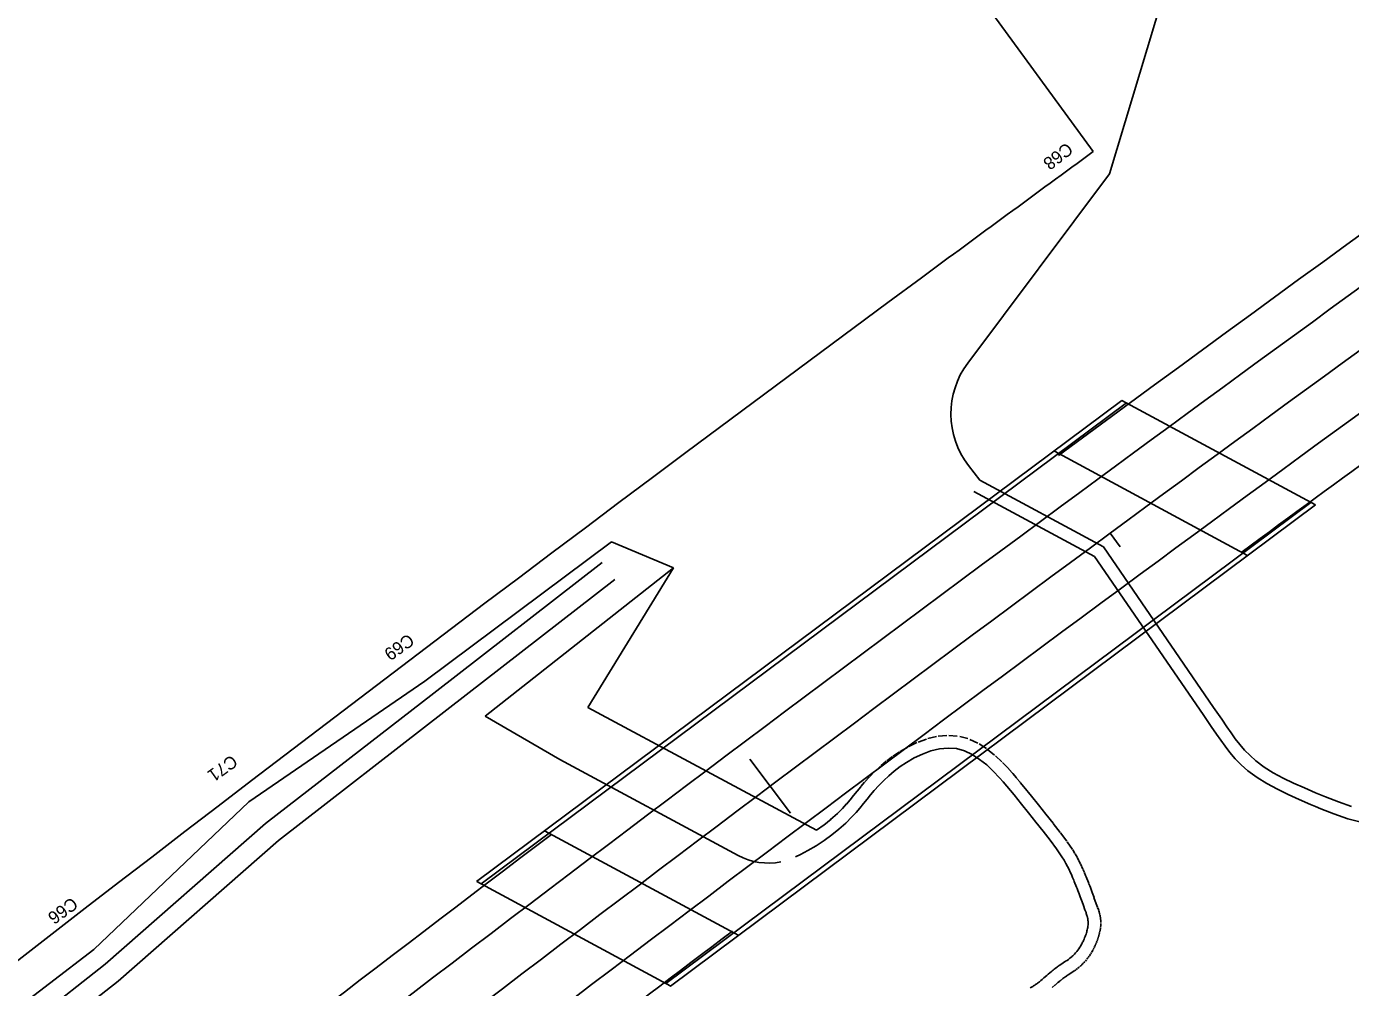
# Model space of a CAD drawing. Extents: x 1469024 to 1473560, y 1105695 to 1109739.
# Drawn here: x 1470861.2 to 1471173.7, y 1107588.4 to 1107815.4 of the extents above; entities that cross this region are included whole.
import ezdxf

# ---------------------------------------------------------------- set-up
doc = ezdxf.new("R2010")
doc.units = 0
for name, color, linetype in [('RD_HC_CL_Rel', 7, 'Continuous'), ('RD_HC_Data_Tic_Rel', 7, 'Continuous'), ('RD_PD_Bridge', 7, 'Continuous'), ('RD_PD_CstnLmt', 7, 'Continuous'), ('RD_PD_CstnLmt_TX', 7, 'Continuous'), ('RD_PD_DR_Ditch', 7, 'Continuous'), ('RD_PD_DR_ErosCtrl', 7, 'Continuous'), ('RD_PD_Final_TrvlWay', 7, 'Continuous'), ('RD_PD_GR', 7, 'Continuous'), ('RD_PD_RW', 7, 'Continuous')]:
    doc.layers.add(name, color=color, linetype=linetype)

msp = doc.modelspace()

# ---------------------------------------------------------------- linework, layer by layer
at = {"layer": 'RD_HC_CL_Rel'}
for start, end in [(123.079489, 126.41418), (126.41418, 130.102414)]:
    msp.add_arc((1477943.58, 1098441.09), 11500, start, end, dxfattribs=at)
at = {"layer": 'RD_HC_Data_Tic_Rel'}
for p, q in [((1471116.97, 1107695.68), (1471119.34, 1107692.46)), ((1471036.75, 1107635.97), (1471031.95, 1107642.36)), ((1471036.75, 1107635.97), (1471041.56, 1107629.57))]:
    msp.add_line(p, q, dxfattribs=at)
at = {"layer": 'RD_PD_Bridge'}
for p, q in [((1470967.44, 1107613.45), (1471119.73, 1107727.07)), ((1471119.73, 1107727.07), (1471165.47, 1107702.37)), ((1470968.54, 1107612.86), (1471120.82, 1107726.48)), ((1471103.83, 1107715.06), (1471149.46, 1107690.41)), ((1471012.11, 1107589.33), (1471164.39, 1107702.95)), ((1471013.2, 1107588.74), (1471165.48, 1107702.36)), ((1470983.45, 1107625.44), (1471029.3, 1107600.68)), ((1470967.52, 1107613.41), (1471013.27, 1107588.7))]:
    msp.add_line(p, q, dxfattribs=at)
at = {"layer": 'RD_PD_CstnLmt'}
for p, q in [((1471135.06, 1107841.18), (1471116.88, 1107780.53)), ((1471116.88, 1107780.53), (1471083.39, 1107735.89)), ((1471086.23, 1107708.2), (1471083.55, 1107711.67)), ((1471115.39, 1107692.51), (1471086.23, 1107708.2)), ((1470955.2, 1107660.78), (1470999.28, 1107693.67)), ((1470999.28, 1107693.67), (1471013.93, 1107687.49)), ((1471013.93, 1107687.49), (1470969.48, 1107652.47)), ((1470913.68, 1107632.27), (1470955.2, 1107660.78)), ((1471068.9, 1107641.54), (1471070.74, 1107642.61)), ((1471070.74, 1107642.61), (1471072.68, 1107643.53)), ((1471072.68, 1107643.53), (1471074.68, 1107644.26)), ((1471074.68, 1107644.26), (1471076.7, 1107644.75)), ((1471076.7, 1107644.75), (1471078.72, 1107644.95)), ((1471078.72, 1107644.95), (1471080.69, 1107644.81)), ((1471080.69, 1107644.81), (1471082.61, 1107644.28)), ((1471082.61, 1107644.28), (1471084.44, 1107643.42)), ((1471084.44, 1107643.42), (1471086.19, 1107642.29)), ((1471064.75, 1107638.43), (1471066.04, 1107639.52)), ((1471066.04, 1107639.52), (1471067.43, 1107640.56)), ((1471067.43, 1107640.56), (1471068.9, 1107641.54)), ((1471086.19, 1107642.29), (1471087.85, 1107640.96)), ((1471087.85, 1107640.96), (1471089.41, 1107639.49)), ((1471089.41, 1107639.49), (1471090.87, 1107637.95)), ((1471062.39, 1107636.14), (1471063.53, 1107637.3)), ((1471063.53, 1107637.3), (1471064.75, 1107638.43)), ((1471090.87, 1107637.95), (1471091.76, 1107636.96)), ((1471091.76, 1107636.96), (1471092.62, 1107635.96)), ((1471059.6, 1107632.89), (1471060.45, 1107633.93)), ((1471060.45, 1107633.93), (1471061.31, 1107634.95)), ((1471061.31, 1107634.95), (1471062.39, 1107636.14)), ((1471092.62, 1107635.96), (1471093.47, 1107634.94)), ((1471093.47, 1107634.94), (1471094.31, 1107633.9)), ((1471094.31, 1107633.9), (1471096.07, 1107631.72)), ((1470877.09, 1107597.35), (1470913.68, 1107632.27)), ((1471057.01, 1107629.74), (1471057.91, 1107630.79)), ((1471057.91, 1107630.79), (1471058.76, 1107631.84)), ((1471058.76, 1107631.84), (1471059.6, 1107632.89)), ((1471096.07, 1107631.72), (1471097.74, 1107629.65)), ((1471052.98, 1107625.81), (1471054.58, 1107627.24)), ((1471054.58, 1107627.24), (1471056.04, 1107628.69)), ((1471056.04, 1107628.69), (1471057.01, 1107629.74)), ((1471097.74, 1107629.65), (1471099.48, 1107627.49)), ((1471099.48, 1107627.49), (1471101.21, 1107625.31)), ((1471049.46, 1107623.11), (1471051.27, 1107624.43)), ((1471051.27, 1107624.43), (1471052.98, 1107625.81)), ((1471101.21, 1107625.31), (1471102.85, 1107623.18)), ((1471043.86, 1107619.79), (1471045.66, 1107620.74)), ((1471045.66, 1107620.74), (1471047.59, 1107621.87)), ((1471047.59, 1107621.87), (1471049.46, 1107623.11)), ((1471102.85, 1107623.18), (1471104.34, 1107621.16)), ((1471104.34, 1107621.16), (1471105.6, 1107619.3)), ((1471042.75, 1107619.25), (1471043.86, 1107619.79)), ((1471105.6, 1107619.3), (1471106.12, 1107618.47)), ((1471106.12, 1107618.47), (1471106.57, 1107617.69)), ((1471106.57, 1107617.69), (1471106.96, 1107616.96)), ((1471106.96, 1107616.96), (1471107.3, 1107616.29)), ((1471107.3, 1107616.29), (1471107.59, 1107615.67)), ((1471107.59, 1107615.67), (1471107.84, 1107615.11)), ((1471107.84, 1107615.11), (1471107.95, 1107614.85)), ((1471107.95, 1107614.85), (1471108.14, 1107614.38)), ((1471108.14, 1107614.38), (1471108.41, 1107613.73)), ((1471108.41, 1107613.73), (1471108.53, 1107613.44)), ((1471108.53, 1107613.44), (1471109.09, 1107612.08)), ((1471109.09, 1107612.08), (1471109.19, 1107611.81)), ((1471109.19, 1107611.81), (1471109.38, 1107611.35)), ((1471109.38, 1107611.35), (1471109.53, 1107610.95)), ((1471109.53, 1107610.95), (1471109.68, 1107610.54)), ((1471109.68, 1107610.54), (1471109.93, 1107609.84)), ((1471109.93, 1107609.84), (1471110.36, 1107608.63)), ((1471110.36, 1107608.63), (1471110.67, 1107607.78)), ((1471110.67, 1107607.78), (1471111.05, 1107606.75)), ((1471111.05, 1107606.75), (1471111.22, 1107606.3)), ((1471111.22, 1107606.3), (1471111.3, 1107606.08)), ((1471111.3, 1107606.08), (1471111.37, 1107605.86)), ((1471111.37, 1107605.86), (1471111.45, 1107605.64)), ((1471111.45, 1107605.64), (1471111.52, 1107605.41)), ((1471111.52, 1107605.41), (1471111.56, 1107605.28)), ((1471111.56, 1107605.28), (1471111.6, 1107605.14)), ((1471111.6, 1107605.14), (1471111.63, 1107605)), ((1471111.63, 1107605), (1471111.66, 1107604.85)), ((1471111.59, 1107602), (1471111.53, 1107601.75)), ((1471111.65, 1107602.31), (1471111.59, 1107602)), ((1471111.7, 1107602.61), (1471111.65, 1107602.31)), ((1471111.66, 1107604.85), (1471111.69, 1107604.71)), ((1471111.69, 1107604.71), (1471111.72, 1107604.57)), ((1471111.74, 1107602.92), (1471111.7, 1107602.61)), ((1471111.72, 1107604.57), (1471111.74, 1107604.44)), ((1471111.74, 1107604.44), (1471111.75, 1107604.32)), ((1471111.77, 1107603.22), (1471111.74, 1107602.92)), ((1471111.75, 1107604.32), (1471111.76, 1107604.19)), ((1471111.76, 1107604.19), (1471111.77, 1107604.06)), ((1471111.77, 1107604.06), (1471111.78, 1107603.93)), ((1471111.78, 1107603.51), (1471111.77, 1107603.22)), ((1471111.78, 1107603.93), (1471111.79, 1107603.8)), ((1471111.79, 1107603.8), (1471111.78, 1107603.51)), ((1471110.4, 1107598.89), (1471110.29, 1107598.69)), ((1471110.5, 1107599.1), (1471110.4, 1107598.89)), ((1471110.61, 1107599.3), (1471110.5, 1107599.1)), ((1471110.7, 1107599.51), (1471110.61, 1107599.3)), ((1471110.84, 1107599.82), (1471110.7, 1107599.51)), ((1471110.97, 1107600.12), (1471110.84, 1107599.82)), ((1471111.1, 1107600.42), (1471110.97, 1107600.12)), ((1471111.21, 1107600.72), (1471111.1, 1107600.42)), ((1471111.31, 1107601.03), (1471111.21, 1107600.72)), ((1471111.41, 1107601.33), (1471111.31, 1107601.03)), ((1471111.46, 1107601.49), (1471111.41, 1107601.33)), ((1471111.53, 1107601.75), (1471111.46, 1107601.49)), ((1470837.12, 1107566.82), (1470877.09, 1107597.35)), ((1471107.93, 1107595.66), (1471107.8, 1107595.55)), ((1471108.06, 1107595.77), (1471107.93, 1107595.66)), ((1471108.19, 1107595.89), (1471108.06, 1107595.77)), ((1471108.31, 1107596.01), (1471108.19, 1107595.89)), ((1471108.43, 1107596.13), (1471108.31, 1107596.01)), ((1471108.55, 1107596.25), (1471108.43, 1107596.13)), ((1471108.83, 1107596.56), (1471108.55, 1107596.25)), ((1471109.1, 1107596.89), (1471108.83, 1107596.56)), ((1471109.36, 1107597.23), (1471109.1, 1107596.89)), ((1471109.61, 1107597.57), (1471109.36, 1107597.23)), ((1471109.84, 1107597.92), (1471109.61, 1107597.57)), ((1471110.06, 1107598.28), (1471109.84, 1107597.92)), ((1471110.17, 1107598.48), (1471110.06, 1107598.28)), ((1471110.29, 1107598.69), (1471110.17, 1107598.48)), ((1471103.56, 1107592.53), (1471103.32, 1107592.34)), ((1471103.81, 1107592.72), (1471103.56, 1107592.53)), ((1471104.05, 1107592.91), (1471103.81, 1107592.72)), ((1471104.3, 1107593.09), (1471104.05, 1107592.91)), ((1471104.55, 1107593.27), (1471104.3, 1107593.09)), ((1471104.76, 1107593.42), (1471104.55, 1107593.27)), ((1471104.97, 1107593.57), (1471104.76, 1107593.42)), ((1471105.39, 1107593.85), (1471104.97, 1107593.57)), ((1471106.49, 1107594.59), (1471105.39, 1107593.85)), ((1471106.83, 1107594.82), (1471106.49, 1107594.59)), ((1471107.16, 1107595.05), (1471106.83, 1107594.82)), ((1471107.48, 1107595.3), (1471107.16, 1107595.05)), ((1471107.8, 1107595.55), (1471107.48, 1107595.3)), ((1471099.85, 1107589.41), (1471099.69, 1107589.3)), ((1471100, 1107589.52), (1471099.85, 1107589.41)), ((1471100.16, 1107589.64), (1471100, 1107589.52)), ((1471100.31, 1107589.76), (1471100.16, 1107589.64)), ((1471100.43, 1107589.86), (1471100.31, 1107589.76)), ((1471100.67, 1107590.06), (1471100.43, 1107589.86)), ((1471100.91, 1107590.26), (1471100.67, 1107590.06)), ((1471101.36, 1107590.65), (1471100.91, 1107590.26)), ((1471102.03, 1107591.24), (1471101.36, 1107590.65)), ((1471102.37, 1107591.55), (1471102.03, 1107591.24)), ((1471102.72, 1107591.85), (1471102.37, 1107591.55)), ((1471103.07, 1107592.14), (1471102.72, 1107591.85)), ((1471103.32, 1107592.34), (1471103.07, 1107592.14)), ((1471098.39, 1107588.48), (1471098.12, 1107588.33)), ((1471098.56, 1107588.58), (1471098.39, 1107588.48)), ((1471098.73, 1107588.67), (1471098.56, 1107588.58)), ((1471098.89, 1107588.77), (1471098.73, 1107588.67)), ((1471099.06, 1107588.87), (1471098.89, 1107588.77)), ((1471099.22, 1107588.98), (1471099.06, 1107588.87)), ((1471099.38, 1107589.08), (1471099.22, 1107588.98)), ((1471099.54, 1107589.19), (1471099.38, 1107589.08)), ((1471099.69, 1107589.3), (1471099.54, 1107589.19))]:
    msp.add_line(p, q, dxfattribs=at)
for points in [[(1471115.39, 1107692.51), (1471141.39, 1107654.57), (1471143.33, 1107651.74), (1471144.57, 1107649.94), (1471145.53, 1107648.56), (1471146.54, 1107647.17), (1471147.6, 1107645.8), (1471148.75, 1107644.46), (1471150.02, 1107643.16), (1471151.41, 1107641.93), (1471153.36, 1107640.48), (1471155.51, 1107639.14), (1471157.84, 1107637.88), (1471160.3, 1107636.68), (1471162.85, 1107635.53), (1471165.47, 1107634.41), (1471166.66, 1107633.91), (1471167.87, 1107633.41), (1471170.88, 1107632.22), (1471173.99, 1107631.14)], [(1470969.48, 1107652.47), (1470987.09, 1107642.22)], [(1470987.09, 1107642.22), (1471029.18, 1107619.58)]]:
    msp.add_lwpolyline(points, dxfattribs=at)
for centre, radius, start, end in [((1471099.39, 1107723.88), 20, 143.1262, 217.6395), ((1471036.29, 1107632.79), 15, 241.7286, 281.3604)]:
    msp.add_arc(centre, radius, start, end, dxfattribs=at)
at = {"layer": 'RD_PD_DR_Ditch'}
for p, q in [((1470957.33, 1107657.94), (1470997.06, 1107688.76)), ((1470960.37, 1107653.97), (1471000.08, 1107684.78)), ((1470917.62, 1107627.13), (1470957.35, 1107657.95)), ((1470920.66, 1107623.16), (1470960.37, 1107653.97)), ((1470879.75, 1107593.9), (1470917.62, 1107627.13)), ((1470882.8, 1107589.94), (1470920.66, 1107623.16)), ((1470840.22, 1107562.84), (1470879.75, 1107593.9)), ((1470843.29, 1107558.9), (1470882.8, 1107589.94))]:
    msp.add_line(p, q, dxfattribs=at)
at = {"layer": 'RD_PD_DR_ErosCtrl'}
for p, q in [((1471113.33, 1107690.22), (1471084.81, 1107705.55)), ((1470993.72, 1107654.55), (1471013.93, 1107687.49)), ((1471047.68, 1107625.53), (1470993.72, 1107654.55)), ((1471069.45, 1107645.31), (1471071.39, 1107646.24)), ((1471071.65, 1107646.34), (1471073.64, 1107647.08)), ((1471073.97, 1107647.18), (1471075.99, 1107647.67)), ((1471076.41, 1107647.74), (1471078.42, 1107647.94)), ((1471078.94, 1107647.94), (1471080.91, 1107647.8)), ((1471081.48, 1107647.7), (1471083.4, 1107647.18)), ((1471083.88, 1107647), (1471085.72, 1107646.14)), ((1471086.07, 1107645.94), (1471087.82, 1107644.81)), ((1471064.24, 1107641.92), (1471065.62, 1107642.96)), ((1471065.76, 1107643.06), (1471067.23, 1107644.04)), ((1471067.4, 1107644.14), (1471069.24, 1107645.2)), ((1471088.07, 1107644.63), (1471089.73, 1107643.29)), ((1471089.9, 1107643.14), (1471091.46, 1107641.67)), ((1471060.25, 1107638.24), (1471061.39, 1107639.41)), ((1471061.49, 1107639.5), (1471062.71, 1107640.63)), ((1471062.82, 1107640.73), (1471064.12, 1107641.82)), ((1471091.58, 1107641.56), (1471093.04, 1107640.02)), ((1471093.11, 1107639.95), (1471094, 1107638.96)), ((1471058.15, 1107635.86), (1471059.02, 1107636.89)), ((1471059.09, 1107636.96), (1471060.16, 1107638.15)), ((1471094.04, 1107638.91), (1471094.89, 1107637.91)), ((1471094.92, 1107637.88), (1471095.77, 1107636.86)), ((1471095.79, 1107636.84), (1471096.64, 1107635.8)), ((1471055.58, 1107632.69), (1471056.44, 1107633.74)), ((1471056.42, 1107633.72), (1471057.26, 1107634.77)), ((1471057.27, 1107634.78), (1471058.12, 1107635.82)), ((1471096.65, 1107635.78), (1471098.4, 1107633.6)), ((1471098.4, 1107633.61), (1471100.08, 1107631.53)), ((1471052.47, 1107629.37), (1471053.93, 1107630.81)), ((1471053.83, 1107630.71), (1471054.79, 1107631.76)), ((1471054.73, 1107631.69), (1471055.62, 1107632.74)), ((1471100.08, 1107631.53), (1471101.82, 1107629.37)), ((1471047.68, 1107625.53), (1471049.5, 1107626.85)), ((1471049.39, 1107626.76), (1471051.1, 1107628.15)), ((1471050.99, 1107628.05), (1471052.59, 1107629.48)), ((1471101.83, 1107629.36), (1471103.56, 1107627.18)), ((1471103.58, 1107627.15), (1471105.23, 1107625.01)), ((1471105.27, 1107624.96), (1471106.76, 1107622.93)), ((1471106.82, 1107622.84), (1471108.08, 1107620.99)), ((1471108.15, 1107620.88), (1471108.67, 1107620.05)), ((1471108.72, 1107619.97), (1471109.17, 1107619.19)), ((1471109.21, 1107619.11), (1471109.6, 1107618.39)), ((1471109.64, 1107618.31), (1471109.98, 1107617.64)), ((1471110.01, 1107617.57), (1471110.3, 1107616.95)), ((1471110.33, 1107616.89), (1471110.58, 1107616.32)), ((1471110.6, 1107616.28), (1471110.71, 1107616.03)), ((1471110.72, 1107616), (1471110.92, 1107615.53)), ((1471110.93, 1107615.5), (1471111.19, 1107614.85)), ((1471111.18, 1107614.86), (1471111.3, 1107614.57)), ((1471111.3, 1107614.58), (1471111.86, 1107613.22)), ((1471111.87, 1107613.2), (1471111.98, 1107612.94)), ((1471111.99, 1107612.91), (1471112.17, 1107612.45)), ((1471112.18, 1107612.42), (1471112.33, 1107612.01)), ((1471112.34, 1107611.99), (1471112.49, 1107611.58)), ((1471112.5, 1107611.56), (1471112.75, 1107610.86)), ((1471112.76, 1107610.85), (1471113.19, 1107609.63)), ((1471113.18, 1107609.65), (1471113.49, 1107608.8)), ((1471113.48, 1107608.82), (1471113.87, 1107607.79)), ((1471113.86, 1107607.79), (1471114.03, 1107607.34)), ((1471114.04, 1107607.32), (1471114.12, 1107607.1)), ((1471114.13, 1107607.07), (1471114.21, 1107606.84)), ((1471114.22, 1107606.8), (1471114.3, 1107606.58)), ((1471114.31, 1107606.53), (1471114.38, 1107606.31)), ((1471114.4, 1107606.25), (1471114.44, 1107606.11)), ((1471114.45, 1107606.06), (1471114.49, 1107605.92)), ((1471114.5, 1107605.87), (1471114.54, 1107605.73)), ((1471114.55, 1107605.66), (1471114.59, 1107605.52)), ((1471114.6, 1107605.45), (1471114.63, 1107605.31)), ((1471114.65, 1107605.24), (1471114.67, 1107605.09)), ((1471114.68, 1107605.02), (1471114.7, 1107604.89)), ((1471114.66, 1107602.11), (1471114.61, 1107601.8)), ((1471114.72, 1107602.52), (1471114.68, 1107602.22)), ((1471114.71, 1107604.82), (1471114.73, 1107604.69)), ((1471114.76, 1107602.94), (1471114.73, 1107602.64)), ((1471114.74, 1107604.62), (1471114.75, 1107604.5)), ((1471114.76, 1107604.42), (1471114.77, 1107604.3)), ((1471114.77, 1107604.22), (1471114.78, 1107604.09)), ((1471114.78, 1107603.36), (1471114.77, 1107603.07)), ((1471114.78, 1107604.02), (1471114.78, 1107603.89)), ((1471114.79, 1107603.78), (1471114.78, 1107603.5)), ((1471113.73, 1107598.93), (1471113.6, 1107598.63)), ((1471113.88, 1107599.3), (1471113.76, 1107599)), ((1471114.02, 1107599.67), (1471113.9, 1107599.37)), ((1471114.15, 1107600.04), (1471114.04, 1107599.74)), ((1471114.27, 1107600.42), (1471114.17, 1107600.12)), ((1471114.34, 1107600.66), (1471114.29, 1107600.49)), ((1471114.42, 1107600.97), (1471114.36, 1107600.72)), ((1471114.5, 1107601.3), (1471114.44, 1107601.05)), ((1471114.59, 1107601.7), (1471114.52, 1107601.39)), ((1471112.06, 1107595.84), (1471111.81, 1107595.49)), ((1471112.35, 1107596.28), (1471112.11, 1107595.92)), ((1471112.61, 1107596.71), (1471112.4, 1107596.36)), ((1471112.77, 1107596.98), (1471112.65, 1107596.78)), ((1471112.91, 1107597.23), (1471112.8, 1107597.02)), ((1471113.04, 1107597.48), (1471112.93, 1107597.27)), ((1471113.17, 1107597.73), (1471113.06, 1107597.52)), ((1471113.29, 1107597.97), (1471113.19, 1107597.77)), ((1471113.41, 1107598.22), (1471113.31, 1107598.01)), ((1471113.57, 1107598.57), (1471113.43, 1107598.27)), ((1471108.9, 1107592.61), (1471108.56, 1107592.37)), ((1471109.28, 1107592.9), (1471108.96, 1107592.65)), ((1471109.68, 1107593.21), (1471109.36, 1107592.96)), ((1471109.87, 1107593.38), (1471109.74, 1107593.26)), ((1471110.04, 1107593.52), (1471109.92, 1107593.41)), ((1471110.21, 1107593.68), (1471110.09, 1107593.56)), ((1471110.38, 1107593.83), (1471110.25, 1107593.72)), ((1471110.54, 1107594), (1471110.42, 1107593.88)), ((1471110.7, 1107594.16), (1471110.58, 1107594.04)), ((1471111.05, 1107594.55), (1471110.77, 1107594.23)), ((1471111.41, 1107594.97), (1471111.14, 1107594.65)), ((1471111.75, 1107595.4), (1471111.49, 1107595.07)), ((1471104.68, 1107589.57), (1471104.33, 1107589.27)), ((1471105, 1107589.84), (1471104.65, 1107589.55)), ((1471105.21, 1107590.01), (1471104.97, 1107589.82)), ((1471105.43, 1107590.19), (1471105.18, 1107589.99)), ((1471105.64, 1107590.35), (1471105.4, 1107590.16)), ((1471105.86, 1107590.52), (1471105.62, 1107590.33)), ((1471106.08, 1107590.68), (1471105.84, 1107590.5)), ((1471106.3, 1107590.84), (1471106.06, 1107590.66)), ((1471106.49, 1107590.97), (1471106.28, 1107590.82)), ((1471106.68, 1107591.1), (1471106.47, 1107590.96)), ((1471107.08, 1107591.38), (1471106.65, 1107591.09)), ((1471108.15, 1107592.09), (1471107.05, 1107591.36)), ((1471108.52, 1107592.34), (1471108.18, 1107592.11)), ((1471104.01, 1107589), (1471103.34, 1107588.4)), ((1471104.35, 1107589.29), (1471104, 1107588.99))]:
    msp.add_line(p, q, dxfattribs=at)
msp.add_lwpolyline([(1471113.33, 1107690.22), (1471138.92, 1107652.88), (1471140.86, 1107650.04), (1471142.1, 1107648.24), (1471143.09, 1107646.82), (1471144.14, 1107645.37), (1471145.28, 1107643.9), (1471146.54, 1107642.43), (1471147.94, 1107640.99), (1471149.52, 1107639.6), (1471151.67, 1107638), (1471154, 1107636.55), (1471156.47, 1107635.21), (1471159.03, 1107633.96), (1471161.65, 1107632.78), (1471164.3, 1107631.65), (1471165.51, 1107631.14), (1471166.74, 1107630.63), (1471169.83, 1107629.4), (1471173.12, 1107628.27), (1471176.57, 1107627.36)], dxfattribs=at)
at = {"layer": 'RD_PD_Final_TrvlWay'}
for radius, start, end in [(11512, 123.079489, 126.41418), (11488, 123.079489, 126.41418), (11512, 126.41418, 130.102414), (11488, 126.41418, 130.102414)]:
    msp.add_arc((1477943.58, 1098441.09), radius, start, end, dxfattribs=at)
at = {"layer": 'RD_PD_GR'}
for radius, start, end in [(11522, 124.172166, 126.408649), (11478, 125.874656, 126.301954), (11522, 127.151906, 128.656189), (11478, 127.050651, 128.032489)]:
    msp.add_arc((1477943.58, 1098441.09), radius, start, end, dxfattribs=at)
at = {"layer": 'RD_PD_RW'}
msp.add_line((1471113.01, 1107785.82), (1471083.51, 1107826.19), dxfattribs=at)
for start, end in [(126.165068, 126.41418), (126.41418, 129.547337)]:
    msp.add_arc((1477943.58, 1098441.09), 11575, start, end, dxfattribs=at)

# ---------------------------------------------------------------- texts
at = {"layer": 'RD_PD_CstnLmt_TX'}
for s, rotation, p in [('C68', 217.6765, (1471106.72, 1107788.14)), ('C69', 215.4828, (1470951.31, 1107672.13)), ('C71', 215.7319, (1470909.6, 1107643.51)), ('C66', 215.981, (1470871.88, 1107609.9))]:
    msp.add_text(s, height=3, rotation=rotation, dxfattribs=at).set_placement(p)

doc.saveas('drawing.dxf')
